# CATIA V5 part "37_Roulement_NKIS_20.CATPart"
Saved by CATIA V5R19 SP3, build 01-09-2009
Part number: 37_Roulement_NKIS_20
Bounding box of the stored display mesh (mm): x 0 to 20, y -21 to 21, z -21 to 21
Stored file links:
  C:\Users\Frédéric\Documents\WF\STSCPI 09-11\Projets\Projet multiplicateur eolienne\Maquette eolienne\Standard\37_Roulement_NKIS_20.CATPart
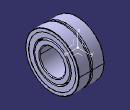
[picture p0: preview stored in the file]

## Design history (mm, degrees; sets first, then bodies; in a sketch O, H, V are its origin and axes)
AxisSystem1: origin (0, 0, 0), X (1, 0, 0), Y (0, 1, 0), Z (0, 0, 1)
Body1 "1" (main body)
  Solid1: solid without history
Body2 "2"
  Solid2: solid without history
Body3 "3"
  Solid3: solid without history
Body4 "4"
  Solid4: solid without history
Body5 "5"
  Solid5: solid without history
Body6 "6"
  Solid6: solid without history
Body7 "7"
  Solid7: solid without history
Body8 "8"
  Solid8: solid without history
Body9 "9"
  Solid9: solid without history
Body10 "10"
  Solid10: solid without history
Body11 "11"
  Solid11: solid without history
Body12 "12"
  Solid12: solid without history
Body13 "13"
  Solid13: solid without history
Body14 "14"
  Solid14: solid without history
Body15 "15"
  Solid15: solid without history
Body16 "16"
  Solid16: solid without history
Body17 "17"
  Solid17: solid without history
